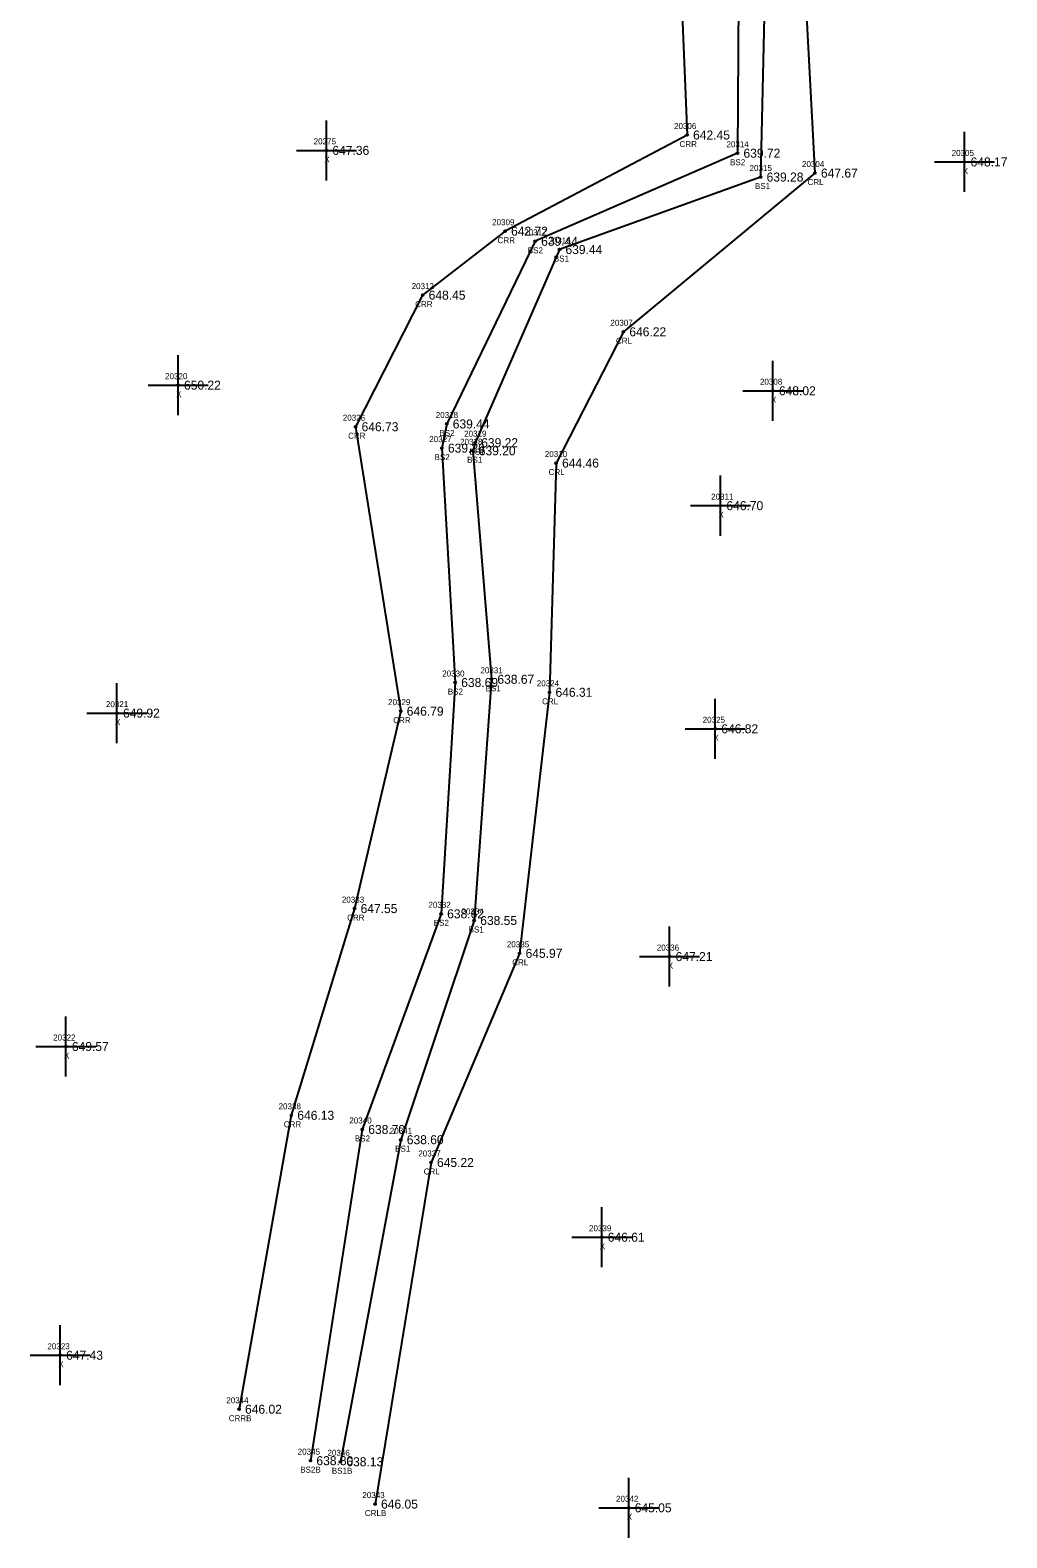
# Model space of a CAD drawing. Extents: x 1655675 to 1657082, y 1004080 to 1005193.
# Drawn here: x 1656261.9 to 1656424.6, y 1004080.2 to 1004331.4 of the extents above; entities that cross this region are included whole.
import ezdxf

# ---------------------------------------------------------------- set-up
doc = ezdxf.new("R2010")
doc.units = 0
for name, color, linetype in [('RD_DTM_BkLn2', 7, 'Continuous'), ('RD_DTM_BkLn_txCode', 7, 'Continuous'), ('RD_EX_H2O', 7, 'Continuous'), ('RD_EX_H2O_txCode', 7, 'Continuous'), ('RD_EX_Misc', 7, 'Continuous'), ('RD_EX_Misc_txCode', 7, 'Continuous'), ('RD_EX_TX_H2O_ELEV', 7, 'Continuous'), ('RD_EX_TX_Misc_ELEV', 7, 'Continuous'), ('RD_SMD_Locator', 7, 'Continuous')]:
    doc.layers.add(name, color=color, linetype=linetype)

msp = doc.modelspace()

# ---------------------------------------------------------------- linework, layer by layer
at = {"layer": 'RD_DTM_BkLn2'}
for points in [[(1656378.15, 1004634.61), (1656371.15, 1004611.72), (1656366.08, 1004597.97), (1656363.03, 1004587.4), (1656375.22, 1004569.39), (1656366.08, 1004537.76), (1656362.3, 1004497.38), (1656381.11, 1004491.46), (1656375.28, 1004468.1), (1656345.39, 1004438.43), (1656334.86, 1004382.95), (1656380.08, 1004353.56), (1656379.77, 1004310.89), (1656346.07, 1004296.22), (1656331.34, 1004265.79), (1656330.54, 1004261.76), (1656332.75, 1004222.72), (1656330.41, 1004184.19), (1656317.27, 1004148.27), (1656308.63, 1004093.1)], [(1656390.72, 1004627.52), (1656381.93, 1004608.13), (1656373.56, 1004597.19), (1656367.78, 1004593.37), (1656379.3, 1004569.5), (1656369.46, 1004537.13), (1656365.12, 1004507.78), (1656384.52, 1004493.19), (1656384.06, 1004470.18), (1656351.72, 1004440.58), (1656340.38, 1004384.23), (1656384.75, 1004357.9), (1656383.63, 1004306.92), (1656350.12, 1004294.84), (1656336.08, 1004262.67), (1656335.68, 1004261.32), (1656338.78, 1004223.26), (1656335.92, 1004183.08), (1656323.69, 1004146.56), (1656313.62, 1004092.92)]]:
    msp.add_lwpolyline(points, dxfattribs=at)
at = {"layer": 'RD_EX_H2O'}
for points in [[(1656368.16, 1004641.29), (1656361.32, 1004615.92), (1656361.94, 1004600.44), (1656360.19, 1004590.3), (1656364.85, 1004571.61), (1656358.83, 1004539.66), (1656356.39, 1004495.48), (1656374.15, 1004488.29), (1656360.29, 1004470.44), (1656342.68, 1004443.17), (1656328, 1004380.72), (1656370, 1004347.54), (1656371.38, 1004313.92), (1656341.06, 1004297.9), (1656327.33, 1004287.25), (1656316.16, 1004265.33), (1656323.68, 1004217.95), (1656315.99, 1004185.06), (1656305.45, 1004150.63), (1656296.74, 1004101.67)], [(1656396.09, 1004633.07), (1656388.01, 1004605.83), (1656383, 1004600.69), (1656372.14, 1004591.42), (1656381.32, 1004569.61), (1656373.51, 1004535.02), (1656369.64, 1004512.2), (1656394.86, 1004499.5), (1656391.61, 1004464.63), (1656362.04, 1004437.06), (1656349.14, 1004389.09), (1656389.79, 1004361.99), (1656392.68, 1004307.58), (1656360.76, 1004281.14), (1656349.55, 1004259.28), (1656348.46, 1004221.09), (1656343.48, 1004177.61), (1656328.72, 1004142.77), (1656319.4, 1004085.87)]]:
    msp.add_lwpolyline(points, dxfattribs=at)
at = {"layer": 'RD_EX_Misc'}
for p, q in [((1656311.29, 1004306.36), (1656311.29, 1004316.36)), ((1656417.61, 1004304.43), (1656417.61, 1004314.43)), ((1656306.29, 1004311.36), (1656316.29, 1004311.36)), ((1656412.61, 1004309.43), (1656422.61, 1004309.43)), ((1656286.58, 1004267.25), (1656286.58, 1004277.25)), ((1656385.68, 1004266.32), (1656385.68, 1004276.32)), ((1656281.58, 1004272.25), (1656291.58, 1004272.25)), ((1656380.68, 1004271.32), (1656390.68, 1004271.32)), ((1656376.93, 1004247.18), (1656376.93, 1004257.18)), ((1656371.93, 1004252.18), (1656381.93, 1004252.18)), ((1656276.41, 1004212.62), (1656276.41, 1004222.62)), ((1656376.08, 1004210.01), (1656376.08, 1004220.01)), ((1656271.41, 1004217.62), (1656281.41, 1004217.62)), ((1656371.08, 1004215.01), (1656381.08, 1004215.01)), ((1656368.47, 1004172.07), (1656368.47, 1004182.07)), ((1656363.47, 1004177.07), (1656373.47, 1004177.07)), ((1656267.9, 1004157.09), (1656267.9, 1004167.09)), ((1656262.9, 1004162.09), (1656272.9, 1004162.09)), ((1656357.16, 1004125.32), (1656357.16, 1004135.32)), ((1656352.16, 1004130.32), (1656362.16, 1004130.32)), ((1656266.94, 1004105.66), (1656266.94, 1004115.66)), ((1656261.94, 1004110.66), (1656271.94, 1004110.66)), ((1656361.66, 1004080.25), (1656361.66, 1004090.25)), ((1656356.66, 1004085.25), (1656366.66, 1004085.25))]:
    msp.add_line(p, q, dxfattribs=at)
at = {"layer": 'RD_SMD_Locator'}
for centre in [(1656371.38, 1004313.92), (1656311.29, 1004311.36), (1656379.77, 1004310.89), (1656417.61, 1004309.43), (1656383.63, 1004306.92), (1656392.68, 1004307.58), (1656341.06, 1004297.9), (1656346.07, 1004296.22), (1656350.12, 1004294.84), (1656327.33, 1004287.25), (1656360.76, 1004281.14), (1656286.58, 1004272.25), (1656385.68, 1004271.32), (1656316.16, 1004265.33), (1656331.34, 1004265.79), (1656330.54, 1004261.76), (1656336.08, 1004262.67), (1656335.68, 1004261.32), (1656349.55, 1004259.28), (1656376.93, 1004252.18), (1656332.75, 1004222.72), (1656338.78, 1004223.26), (1656348.46, 1004221.09), (1656276.41, 1004217.62), (1656323.68, 1004217.95), (1656376.08, 1004215.01), (1656315.99, 1004185.06), (1656330.41, 1004184.19), (1656335.92, 1004183.08), (1656343.48, 1004177.61), (1656368.47, 1004177.07), (1656267.9, 1004162.09), (1656305.45, 1004150.63), (1656317.27, 1004148.27), (1656323.69, 1004146.56), (1656328.72, 1004142.77), (1656357.16, 1004130.32), (1656266.94, 1004110.66), (1656296.74, 1004101.67), (1656308.63, 1004093.1), (1656313.62, 1004092.92), (1656319.4, 1004085.87), (1656361.66, 1004085.25)]:
    msp.add_circle(centre, 0.15, dxfattribs=at)

# ---------------------------------------------------------------- texts
at = {"layer": 'RD_DTM_BkLn_txCode'}
for s, p in [('20314', (1656377.94, 1004311.89)), ('BS2', (1656378.54, 1004308.89)), ('20315', (1656381.79, 1004307.92)), ('BS1', (1656382.68, 1004304.92)), ('20317', (1656344.24, 1004297.22)), ('20316', (1656348.27, 1004295.84)), ('BS2', (1656344.84, 1004294.22)), ('BS1', (1656349.18, 1004292.84)), ('20318', (1656329.51, 1004266.79)), ('BS2', (1656330.12, 1004263.79)), ('20319', (1656334.24, 1004263.67)), ('20327', (1656328.42, 1004262.76)), ('20328', (1656333.57, 1004262.32)), ('BS1', (1656335.13, 1004260.67)), ('BS2', (1656329.31, 1004259.76)), ('BS1', (1656334.74, 1004259.32)), ('20330', (1656330.59, 1004223.72)), ('20331', (1656336.94, 1004224.26)), ('BS2', (1656331.52, 1004220.72)), ('BS1', (1656337.83, 1004221.26)), ('20332', (1656328.29, 1004185.19)), ('20334', (1656333.8, 1004184.08)), ('BS2', (1656329.18, 1004182.19)), ('BS1', (1656334.98, 1004181.08)), ('20340', (1656315.11, 1004149.27)), ('20341', (1656321.86, 1004147.56)), ('BS2', (1656316.04, 1004146.27)), ('BS1', (1656322.75, 1004144.56)), ('20345', (1656306.51, 1004094.1)), ('20346', (1656311.47, 1004093.92)), ('BS2B', (1656306.93, 1004091.1)), ('BS1B', (1656312.2, 1004090.92))]:
    msp.add_text(s, height=1, dxfattribs=at).set_placement(p)
at = {"layer": 'RD_EX_H2O_txCode'}
for s, p in [('20306', (1656369.2, 1004314.92)), ('CRR', (1656370.12, 1004311.92)), ('20304', (1656390.52, 1004308.58)), ('CRL', (1656391.45, 1004305.58)), ('20309', (1656338.9, 1004298.9)), ('CRR', (1656339.81, 1004295.9)), ('20312', (1656325.49, 1004288.25)), ('CRR', (1656326.08, 1004285.25)), ('20307', (1656358.6, 1004282.14)), ('CRL', (1656359.53, 1004279.14)), ('20326', (1656314.02, 1004266.33)), ('CRR', (1656314.91, 1004263.33)), ('20310', (1656347.68, 1004260.28)), ('CRL', (1656348.32, 1004257.28)), ('20324', (1656346.34, 1004222.09)), ('20329', (1656321.56, 1004218.95)), ('CRL', (1656347.23, 1004219.09)), ('CRR', (1656322.43, 1004215.95)), ('20333', (1656313.87, 1004186.06)), ('CRR', (1656314.74, 1004183.06)), ('20335', (1656341.36, 1004178.61)), ('CRL', (1656342.25, 1004175.61)), ('20338', (1656303.33, 1004151.63)), ('CRR', (1656304.19, 1004148.63)), ('20337', (1656326.61, 1004143.77)), ('CRL', (1656327.5, 1004140.77)), ('20344', (1656294.62, 1004102.67)), ('CRRB', (1656295.02, 1004099.67)), ('20343', (1656317.28, 1004086.87)), ('CRLB', (1656317.7, 1004083.87))]:
    msp.add_text(s, height=1, dxfattribs=at).set_placement(p)
at = {"layer": 'RD_EX_Misc_txCode'}
for s, p in [('20275', (1656309.17, 1004312.36)), ('X', (1656310.97, 1004309.36)), ('20305', (1656415.45, 1004310.43)), ('X', (1656417.3, 1004307.43)), ('20320', (1656284.42, 1004273.25)), ('20308', (1656383.52, 1004272.32)), ('X', (1656286.26, 1004270.25)), ('X', (1656385.36, 1004269.32)), ('20311', (1656375.38, 1004253.18)), ('X', (1656376.61, 1004250.18)), ('20321', (1656274.57, 1004218.62)), ('X', (1656276.09, 1004215.62)), ('20325', (1656373.97, 1004216.01)), ('X', (1656375.77, 1004213.01)), ('20336', (1656366.33, 1004178.07)), ('X', (1656368.16, 1004175.07)), ('20322', (1656265.78, 1004163.09)), ('X', (1656267.58, 1004160.09)), ('20339', (1656355.04, 1004131.32)), ('X', (1656356.84, 1004128.32)), ('20323', (1656264.82, 1004111.66)), ('X', (1656266.63, 1004108.66)), ('20342', (1656359.54, 1004086.25)), ('X', (1656361.34, 1004083.25))]:
    msp.add_text(s, height=1, dxfattribs=at).set_placement(p)
at = {"layer": 'RD_EX_TX_H2O_ELEV'}
for s, p in [('642.45', (1656372.38, 1004313.17)), ('647.67', (1656393.68, 1004306.83)), ('642.72', (1656342.06, 1004297.15)), ('648.45', (1656328.33, 1004286.5)), ('646.22', (1656361.76, 1004280.39)), ('646.73', (1656317.16, 1004264.58)), ('644.46', (1656350.55, 1004258.53)), ('646.31', (1656349.46, 1004220.34)), ('646.79', (1656324.68, 1004217.2)), ('647.55', (1656316.99, 1004184.31)), ('645.97', (1656344.48, 1004176.86)), ('646.13', (1656306.45, 1004149.88)), ('645.22', (1656329.72, 1004142.02)), ('646.02', (1656297.74, 1004100.92)), ('646.05', (1656320.4, 1004085.12))]:
    msp.add_text(s, height=1.5, dxfattribs=at).set_placement(p)
at = {"layer": 'RD_EX_TX_Misc_ELEV'}
for s, p in [('647.36', (1656312.29, 1004310.61)), ('639.72', (1656380.77, 1004310.14)), ('648.17', (1656418.61, 1004308.68)), ('639.28', (1656384.63, 1004306.17)), ('639.44', (1656347.07, 1004295.47)), ('639.44', (1656351.12, 1004294.09)), ('650.22', (1656287.58, 1004271.5)), ('648.02', (1656386.68, 1004270.57)), ('639.44', (1656332.34, 1004265.04)), ('639.26', (1656331.54, 1004261.01)), ('639.20', (1656336.68, 1004260.57)), ('639.22', (1656337.08, 1004261.92)), ('646.70', (1656377.93, 1004251.43)), ('638.67', (1656339.78, 1004222.51)), ('638.69', (1656333.75, 1004221.97)), ('649.92', (1656277.41, 1004216.87)), ('646.82', (1656377.08, 1004214.26)), ('638.62', (1656331.41, 1004183.44)), ('638.55', (1656336.92, 1004182.33)), ('647.21', (1656369.47, 1004176.32)), ('649.57', (1656268.9, 1004161.34)), ('638.70', (1656318.27, 1004147.52)), ('638.60', (1656324.69, 1004145.81)), ('646.61', (1656358.16, 1004129.57)), ('647.43', (1656267.94, 1004109.91)), ('638.80', (1656309.63, 1004092.35)), ('638.13', (1656314.62, 1004092.17)), ('645.05', (1656362.66, 1004084.5))]:
    msp.add_text(s, height=1.5, dxfattribs=at).set_placement(p)

doc.saveas('drawing.dxf')
